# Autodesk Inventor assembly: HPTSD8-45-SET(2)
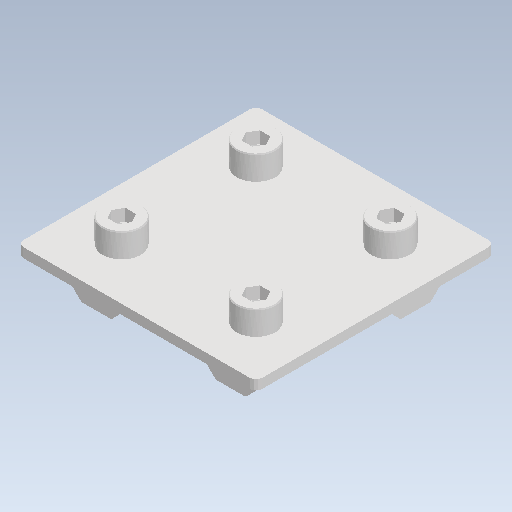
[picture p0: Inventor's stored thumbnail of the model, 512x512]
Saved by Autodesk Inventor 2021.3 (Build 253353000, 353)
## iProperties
Created: 2022-02
Part Number: HPTSD8-45-SET(2)
Document SubType Name: Assembly
Designer: kengo
Author: kengo
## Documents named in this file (4)
- C:\Users\kengo\Documents\S2S_frame\SDC345\frame_misumi_ver12\HPTSD8-45-SET(2).iam
- C:\Users\kengo\Documents\S2S_frame\SDC345\frame_misumi_ver12\HPTSD8-45.ipt
- C:\Users\kengo\Documents\S2S_frame\SDC345\frame_misumi_ver12\HNTT8-8.ipt
- C:\Users\kengo\Documents\S2S_frame\SDC345\frame_misumi_ver12\CBM8-15.ipt
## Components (9 placed, 3 different names)
1. HPTSD8-45
2. HNTT8-8
3. CBM8-15
4. HNTT8-8:1
5. CBM8-15:1
6. HNTT8-8:2
7. CBM8-15:2
8. HNTT8-8:3
9. CBM8-15:3
